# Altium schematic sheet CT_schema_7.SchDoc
size 278 x 170 mm
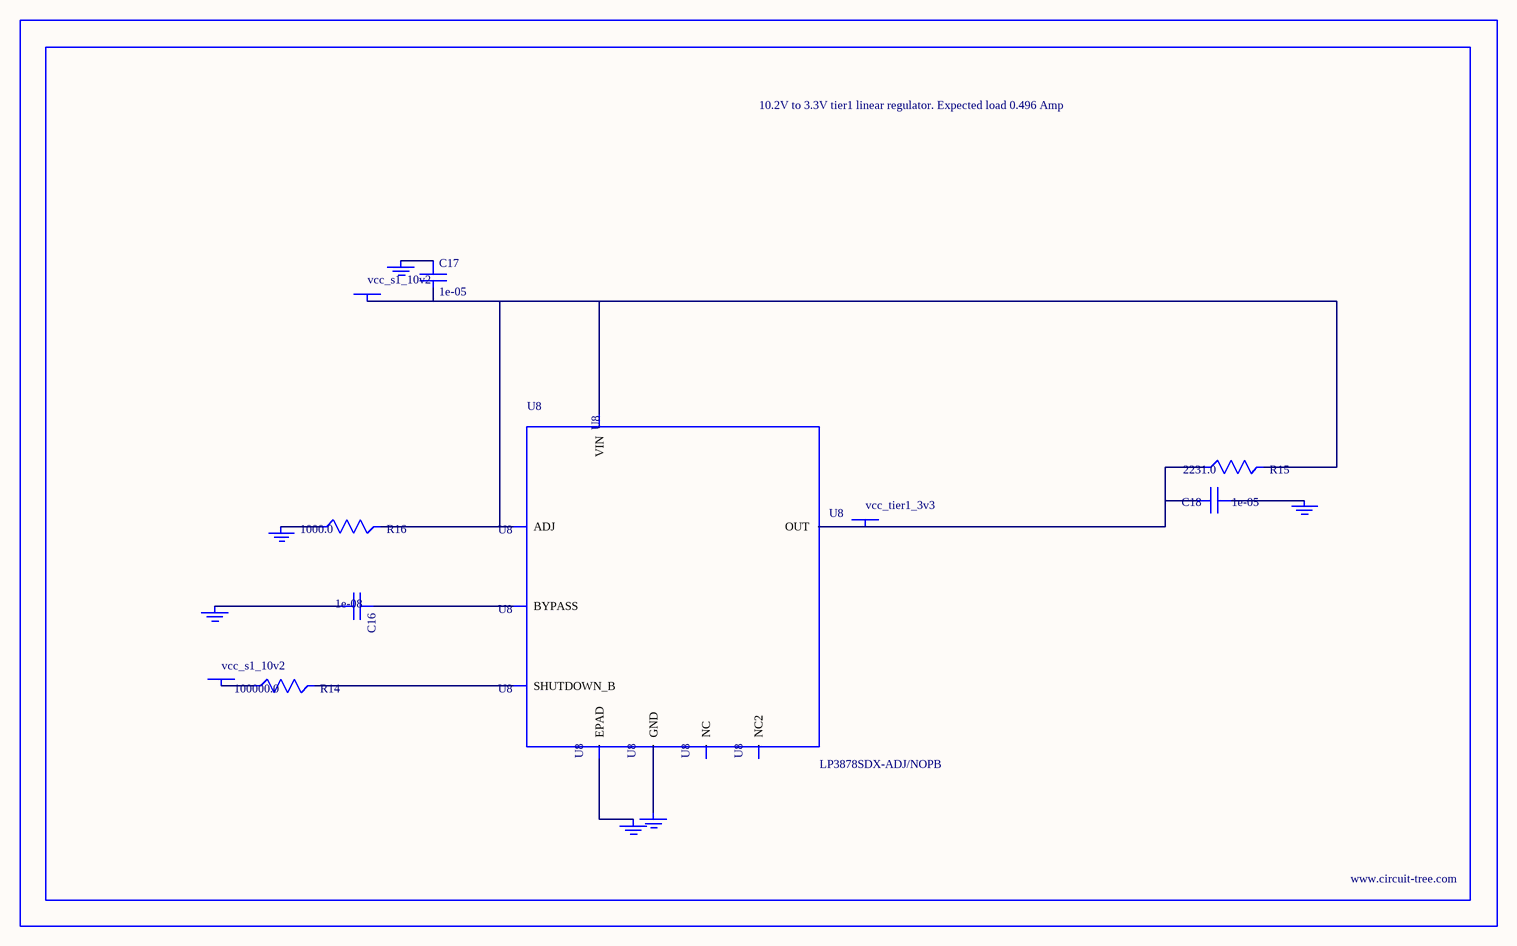
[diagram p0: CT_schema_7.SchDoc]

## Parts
BORDER6  (no value)
C16  1e-08  [C0402]
C17  1e-05  [C1206]
C18  1e-05  [C1210]
GND_INSTANCE_6_0  (no value)
GND_INSTANCE_6_1  (no value)
GND_INSTANCE_6_2  (no value)
GND_INSTANCE_6_3  (no value)
GND_INSTANCE_6_4  (no value)
GND_INSTANCE_6_5  (no value)
POWER_INSTANCE_6_0  vcc_s1_10v2
POWER_INSTANCE_6_1  vcc_s1_10v2
POWER_INSTANCE_6_2  vcc_tier1_3v3
R14  100000.0  [R0603]
R15  2231.0  [R0603]
R16  1000.0  [R0603]
U8  LP3878SDX-ADJ/NOPB  [WSON-8]

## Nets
NetC16_1: C16.1 U8.1(BYPASS)
NetC16_2: C16.2 GND_INSTANCE_6_0.0(GND)
NetC17_1: C17.1 GND_INSTANCE_6_1.0(GND)
NetC17_2: C17.2 POWER_INSTANCE_6_0.0(PWR) R15.2 R16.2 U8.4(VIN) U8.6(ADJ)
NetC18_1: C18.1 GND_INSTANCE_6_2.0(GND)
NetC18_2: C18.2 POWER_INSTANCE_6_2.0(PWR) R15.1 U8.5(OUT)
NetGND_INSTANCE_6_3_0: GND_INSTANCE_6_3.0(GND) R16.1
NetGND_INSTANCE_6_4_0: GND_INSTANCE_6_4.0(GND) U8.PAD(EPAD)
NetGND_INSTANCE_6_5_0: GND_INSTANCE_6_5.0(GND) U8.3(GND)
NetPOWER_INSTANCE_6_1_0: POWER_INSTANCE_6_1.0(PWR) R14.1
NetR14_2: R14.2 U8.8(SHUTDOWN_B)

Not connected (* = marked no-connect by the designer): U8 2(NC) 7(NC2)

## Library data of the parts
BORDER6 = BORDER_PAGE6
C16 = C0402C103K3RAC
C17 = C1206C106K3RACTU
C18 = GRM32DR61E106MA12L
GND_INSTANCE_6_0-GND_INSTANCE_6_5 = GND
POWER_INSTANCE_6_0-POWER_INSTANCE_6_2 = PWR
R14 = RC0603JR-07100KL
R15 = R15
R16 = RC0603JR-071KL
